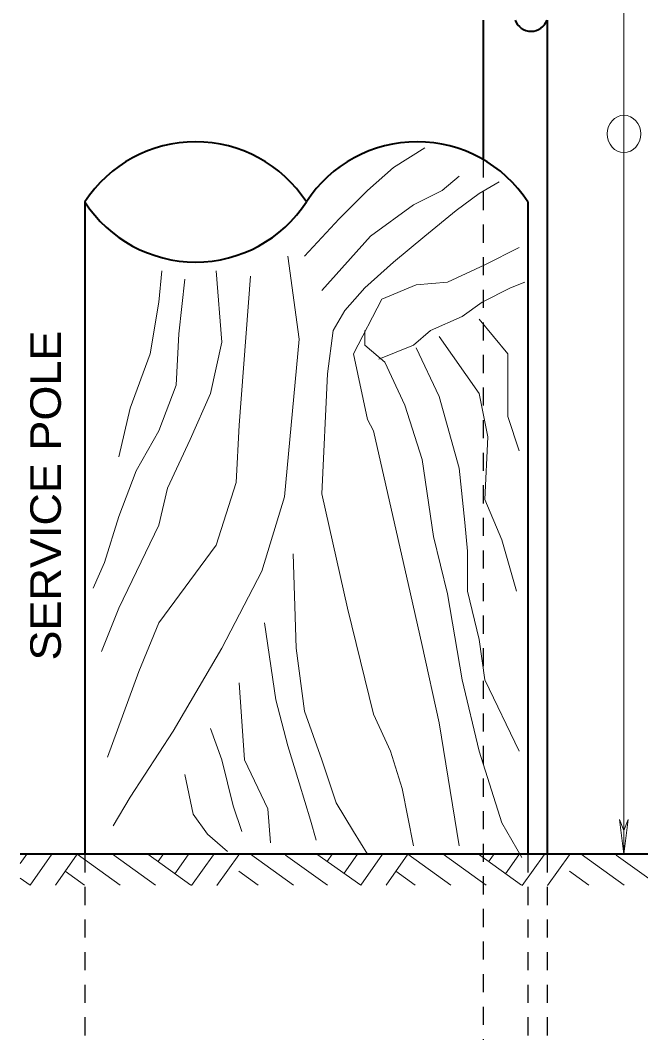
# Model space of a CAD drawing. Extents: x 312583 to 312854, y 144419 to 144597.
# Drawn here: x 312626.85 to 312642.29, y 144512.97 to 144538.14 of the extents above; entities that cross this region are included whole.
import ezdxf

# ---------------------------------------------------------------- set-up
doc = ezdxf.new("R2010")
doc.units = 0
doc.header["$LTSCALE"] = 0.3
doc.linetypes.add('SHORT_DASHED', pattern=[2.7, 1.5, -1.2])
doc.layers.add('1', color=7, linetype='Continuous', lineweight=25)
doc.layers.add('2', color=7, linetype='Continuous', lineweight=13)

msp = doc.modelspace()

# ---------------------------------------------------------------- linework, layer by layer
at = {"layer": '1', "lineweight": 40}
for p, q in [((312638.37, 144538.135), (312638.37, 144534.6773)), ((312639.9646, 144538.135), (312639.9646, 144517.4043)), ((312648.2523, 144517.4043), (312626.8546, 144517.4043))]:
    msp.add_line(p, q, dxfattribs=at)
at = {"layer": '1', "linetype": 'SHORT_DASHED'}
for p, q in [((312638.37, 144534.6773), (312638.37, 144505.9043)), ((312639.9646, 144517.4043), (312639.9646, 144505.9043))]:
    msp.add_line(p, q, dxfattribs=at)
at = {"layer": '1', "lineweight": 13}
for points in [[(312633.931, 144532.27), (312634.7896, 144533.1976), (312635.495, 144533.903), (312636.139, 144534.478), (312636.921, 144534.9686)], [(312634.3603, 144531.419), (312635.5716, 144532.7683), (312636.6373, 144533.5503), (312637.3503, 144533.903), (312637.772, 144534.2633)], [(312634.4983, 144529.349), (312634.644, 144530.4223), (312634.9276, 144530.9206), (312635.426, 144531.488), (312636.139, 144532.1243), (312636.921, 144532.7683), (312637.703, 144533.4046), (312638.2703, 144533.834), (312638.7686, 144534.1176)], [(312635.1423, 144529.8473), (312635.8553, 144531.2043), (312636.7063, 144531.557), (312637.4883, 144531.626), (312638.416, 144532.0553), (312639.267, 144532.4846)], [(312633.5093, 144532.27), (312633.793, 144530.2076), (312633.4326, 144526.29), (312632.8653, 144524.4423), (312631.8686, 144522.5256), (312630.6573, 144520.4633), (312629.5916, 144518.8226), (312629.17, 144518.1096)], [(312631.7306, 144531.9096), (312631.8686, 144530.1386), (312631.585, 144528.8583), (312631.0866, 144527.716), (312630.5193, 144526.5046), (312630.3046, 144525.5846), (312629.308, 144523.5223), (312628.8786, 144522.449)], [(312632.5816, 144531.7716), (312632.298, 144528.0686), (312632.229, 144526.6503), (312631.7306, 144525.0863), (312630.3046, 144523.162), (312629.8063, 144521.9506), (312629.0243, 144519.8193)], [(312630.3736, 144531.9096), (312630.3046, 144531.1276), (312630.09, 144529.8473), (312629.5916, 144528.498), (312629.308, 144527.2866)], [(312630.9486, 144531.7026), (312630.803, 144530.3456), (312630.734, 144529.0653), (312630.3046, 144527.9306), (312629.7373, 144526.934), (312629.308, 144525.7993), (312628.9553, 144524.657), (312628.6716, 144524.0206)], [(312635.7786, 144529.7093), (312636.6373, 144530.062), (312637.059, 144530.4223), (312637.8486, 144530.775), (312638.347, 144531.1276), (312639.0523, 144531.488), (312639.4126, 144531.626)], [(312638.2703, 144530.706), (312638.9833, 144529.8473), (312638.9833, 144528.2833), (312639.267, 144527.4323)], [(312635.426, 144530.4223), (312635.426, 144530.062), (312635.9243, 144529.6403), (312636.4226, 144528.567), (312636.852, 144527.2176), (312637.1356, 144525.301), (312637.4883, 144523.875), (312637.8486, 144521.7436), (312638.2703, 144519.965), (312638.8376, 144518.1863), (312639.336, 144517.3276)], [(312637.2736, 144530.2766), (312638.2703, 144528.8583), (312638.485, 144527.785), (312638.416, 144526.221), (312638.8376, 144525.2243), (312639.198, 144523.944)], [(312636.7063, 144529.993), (312637.2736, 144528.7816), (312637.772, 144527.003), (312637.9176, 144525.6536), (312637.9866, 144524.9406), (312637.9866, 144523.944), (312638.2703, 144522.7403), (312638.416, 144521.7436), (312639.267, 144519.965)], [(312635.1423, 144529.8473), (312635.495, 144528.2143), (312635.6406, 144527.9306), (312636.5683, 144523.875), (312636.852, 144522.5946), (312637.2736, 144520.6703), (312637.772, 144517.6113)], [(312634.4983, 144529.349), (312634.3603, 144526.3666), (312634.9966, 144523.5223), (312635.6406, 144520.885), (312636.07, 144519.965), (312636.3536, 144519.0373), (312636.6373, 144517.6113)], [(312633.6473, 144524.8716), (312633.7163, 144522.5256), (312633.931, 144520.9616), (312634.3603, 144519.7503), (312634.713, 144518.6846), (312635.1423, 144517.9716), (312635.495, 144517.4043)], [(312632.9343, 144523.162), (312633.218, 144521.2453), (312633.5093, 144520.103), (312633.793, 144519.183), (312634.0766, 144518.2553), (312634.2146, 144517.757)], [(312632.298, 144521.667), (312632.436, 144519.7503), (312633.011, 144518.539), (312633.08, 144517.688)], [(312631.585, 144520.5323), (312631.8686, 144519.7503), (312632.1523, 144518.608), (312632.367, 144517.9716)], [(312630.9486, 144519.39), (312631.1556, 144518.401), (312631.516, 144517.9026), (312632.0143, 144517.4733)]]:
    msp.add_lwpolyline(points, dxfattribs=at)
at = {"layer": '1', "lineweight": 40}
for centre, radius, start, end in [((312639.5645, 144538.2894), 0.427, 200.79633, 339.20368), ((312631.2179, 144531.83), 3.2863, 33.0283, 146.97171), ((312636.7283, 144531.83), 3.2863, 33.02829, 146.9717), ((312631.2179, 144535.4124), 3.2863, 213.02829, 326.9717)]:
    msp.add_arc(centre, radius, start, end, dxfattribs=at)
at = {"layer": '2'}
for p, q in [((312641.8736, 144517.4043), (312641.8736, 144544.6516)), ((312641.7663, 144518.2706), (312641.8736, 144517.9946)), ((312641.8736, 144517.4043), (312641.7663, 144518.2706)), ((312641.981, 144518.2706), (312641.8736, 144517.9946)), ((312641.8736, 144517.4043), (312641.981, 144518.2706)), ((312627.0156, 144517.4043), (312626.8546, 144517.1743)), ((312627.6443, 144517.4043), (312627.1, 144516.6376)), ((312628.273, 144517.4043), (312627.7286, 144516.6376)), ((312629.3386, 144516.6376), (312628.273, 144517.4043)), ((312630.2203, 144516.6376), (312629.147, 144517.4043)), ((312631.102, 144516.6376), (312630.0286, 144517.4043)), ((312630.4043, 144517.389), (312630.2816, 144517.2203)), ((312631.033, 144517.389), (312630.7033, 144516.9213)), ((312631.6616, 144517.389), (312631.1173, 144516.63)), ((312632.2903, 144517.389), (312631.746, 144516.63)), ((312633.655, 144516.6376), (312632.5816, 144517.4043)), ((312634.4983, 144516.6376), (312633.4556, 144517.3813)), ((312635.3263, 144516.6376), (312634.2376, 144517.412)), ((312634.6133, 144517.4043), (312634.4906, 144517.228)), ((312635.242, 144517.4043), (312634.9123, 144516.9366)), ((312635.8706, 144517.4043), (312635.3263, 144516.6376)), ((312636.4993, 144517.4043), (312635.955, 144516.6376)), ((312637.565, 144516.6376), (312636.4993, 144517.4043)), ((312638.4466, 144516.6376), (312637.3733, 144517.4043)), ((312639.3283, 144516.6376), (312638.255, 144517.4043)), ((312638.6306, 144517.389), (312638.508, 144517.2203)), ((312639.2593, 144517.389), (312638.9296, 144516.9213)), ((312639.888, 144517.389), (312639.3436, 144516.63)), ((312640.5166, 144517.389), (312639.9723, 144516.63)), ((312641.8813, 144516.6376), (312640.808, 144517.4043)), ((312642.7246, 144516.6376), (312641.682, 144517.3813)), ((312628.457, 144516.6376), (312627.974, 144516.9826)), ((312632.7733, 144516.6376), (312632.2903, 144516.9826)), ((312636.6833, 144516.6376), (312636.2003, 144516.9826)), ((312640.9996, 144516.6376), (312640.5166, 144516.9826)), ((312627.1, 144516.6376), (312626.8546, 144516.814))]:
    msp.add_line(p, q, dxfattribs=at)
at = {"layer": '2', "lineweight": 40}
for p, q in [((312628.4646, 144533.6193), (312628.4646, 144517.4043)), ((312639.4816, 144533.6193), (312639.4816, 144517.4043))]:
    msp.add_line(p, q, dxfattribs=at)
at = {"layer": '2', "linetype": 'SHORT_DASHED', "lineweight": 25}
for p, q in [((312628.4646, 144517.4043), (312628.4646, 144485.2886)), ((312639.4816, 144517.4043), (312639.4816, 144485.2886))]:
    msp.add_line(p, q, dxfattribs=at)
at = {"layer": '2'}
msp.add_ellipse((312641.8746, 144535.3117), major_axis=(0, 0.4636), ratio=0.9, dxfattribs=at)

# ---------------------------------------------------------------- texts
at = {"layer": '2', "width": 1.1}
msp.add_text('SERVICE POLE', height=0.76, rotation=90, dxfattribs=at).set_placement((312627.865, 144522.2212))

doc.saveas('drawing.dxf')
